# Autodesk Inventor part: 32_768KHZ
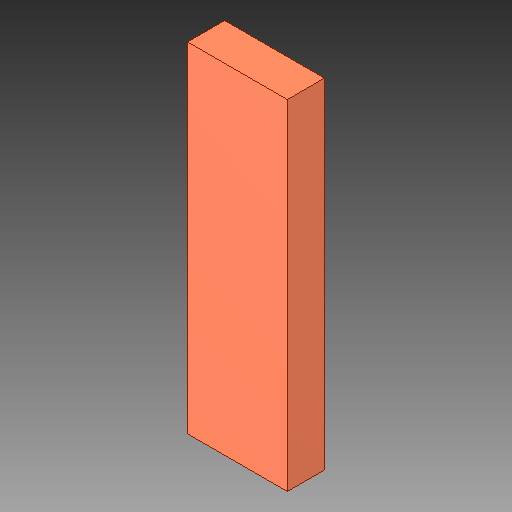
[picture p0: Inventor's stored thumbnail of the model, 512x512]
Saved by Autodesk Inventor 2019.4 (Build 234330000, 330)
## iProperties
Created: 2019-11
Part Number: 32_768KHZ
Material: Generic
Document SubType Name: Modeling
Designer: Willist
Density: 1 g/cm^3
Appearance: CRYSTAL-SMD-2X6-CYL, 32_768KHZ
Author: Willist
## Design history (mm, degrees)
sketch "CRYSTAL-SMD-2X6-CYL, 32_768KHZ_77"
  geometry: L1 (-1.42, 8)-(1.27, 8); L2 (1.27, 8)-(1.27, -1.15); L3 (1.27, -1.15)-(-1.42, -1.15); L4 (-1.42, -1.15)-(-1.42, 8)
  constraints: 8 end point
extrude "Extrusion1" join sketch "CRYSTAL-SMD-2X6-CYL, 32_768KHZ_77" distance "d0" = 1; taper "d1" = 0 deg
body "Solid1"
